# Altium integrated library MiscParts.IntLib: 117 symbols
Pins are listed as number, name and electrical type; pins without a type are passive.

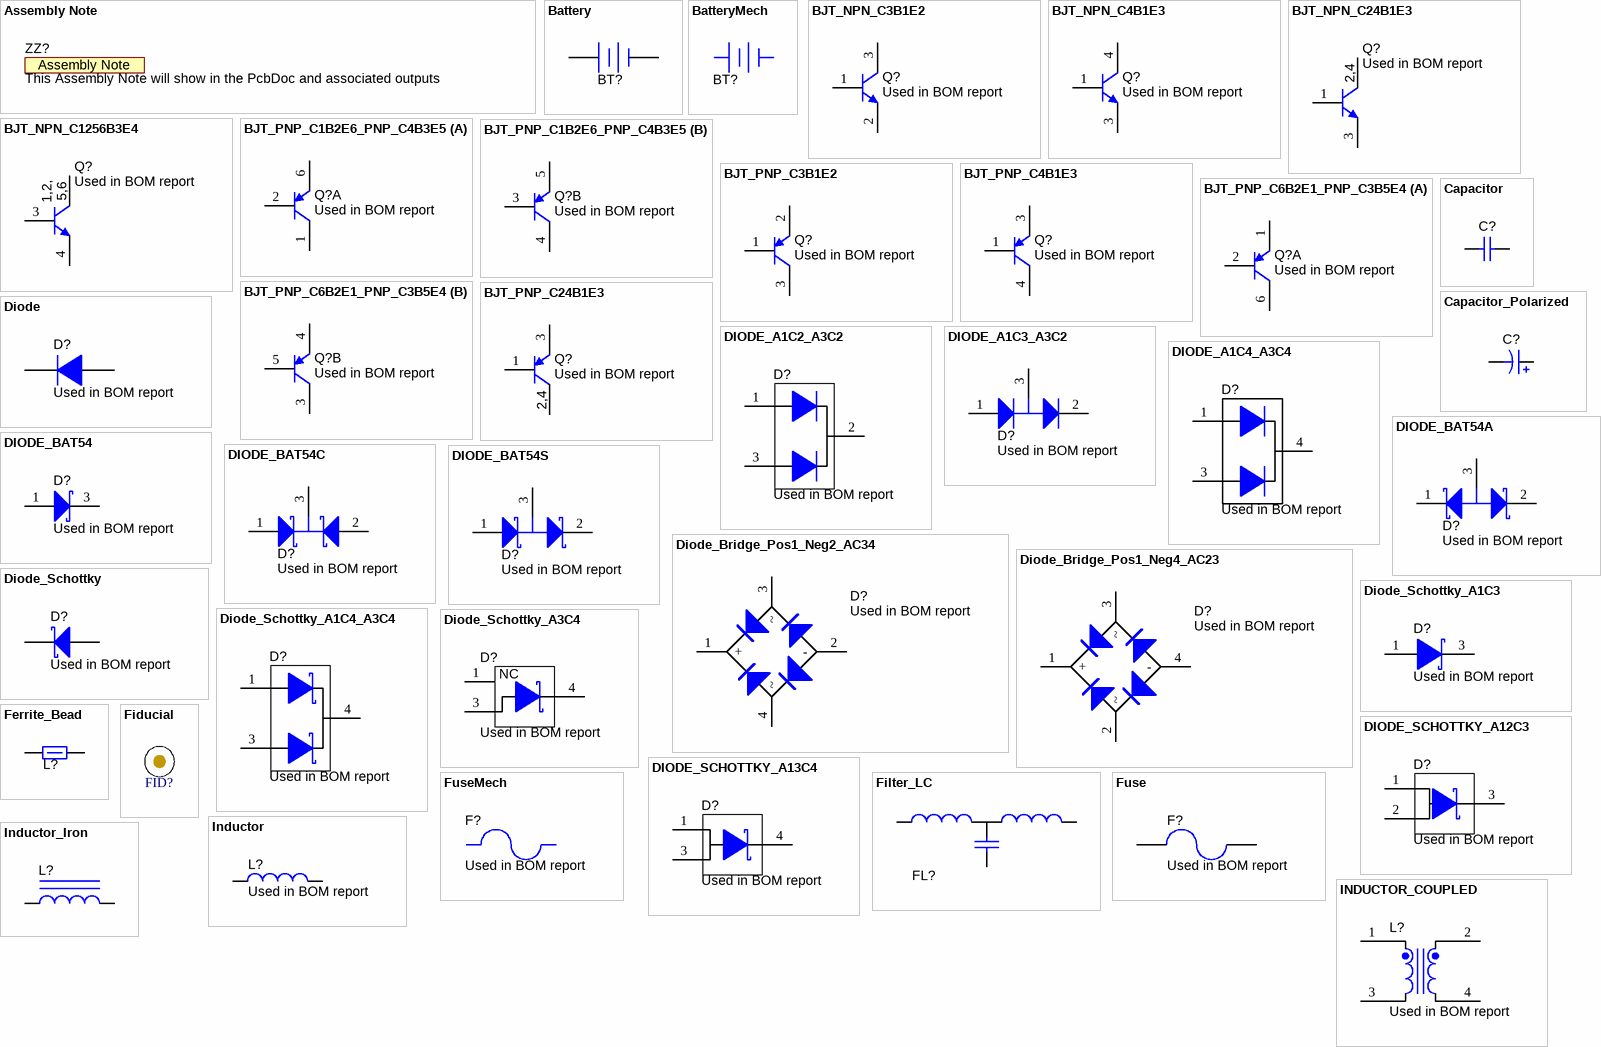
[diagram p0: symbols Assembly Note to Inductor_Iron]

## Assembly Note
designator ZZ?, comment This Assembly Note will show in the PcbDoc and associated outputs  (no BOM)
SymbolCreator: codlsc
footprint AssemblyNote

## Battery
designator BT?, comment Used in BOM report  (value not drawn)
Battery, [Technology], xV, xxmAh; U/M: EA
pins: 1 +, 2 -

## BatteryMech
designator BT?, comment Used in BOM report  (value not drawn)  (mechanical)
Battery, [Technology], xV, xxmAh; SymbolCreator: a0412235; U/M: EA

## BJT_NPN_C3B1E2
designator Q?, comment Used in BOM report
Transistor, NPN, xxV, xA, [PackageReference]; CompType: Bipolar Transistor; U/M: EA
simulation model NPN (Altium default NPN model)
pins: 1 B, 2 E, 3 C

## BJT_NPN_C4B1E3
designator Q?, comment Used in BOM report
Transistor, NPN, xxV, xA, [PackageReference]; CompType: Bipolar Transistor; U/M: EA
simulation model NPN (Altium default NPN model)
pins: 1 B, 3 E, 4 C

## BJT_NPN_C24B1E3
designator Q?, comment Used in BOM report
Transistor, NPN, xxV, xA, [PackageReference]; SymbolCreator: a0412235; CompType: Bipolar Transistor; U/M: EA
footprint SOT-89-3
simulation model NPN (Altium default NPN model)
pins: 1 B, 2 C, 3 E, 4 C

## BJT_NPN_C1256B3E4
designator Q?, comment Used in BOM report
Transistor, NPN, xxV, xA, [PackageReference]; CompType: Bipolar Transistor; U/M: EA
simulation model NPN (Altium default NPN model)
pins: 1 C, 2 C, 3 B, 4 E, 5 C, 6 C

## BJT_PNP_C1B2E6_PNP_C4B3E5
designator Q?, comment Used in BOM report
Transistor, NPN, xxV, xA, [PackageReference]; CompType: Bipolar Transistor; U/M: EA
part A pins: 1 C, 2 B, 6 E
part B pins: 3 B, 4 C, 5 E

## BJT_PNP_C3B1E2
designator Q?, comment Used in BOM report
Transistor, NPN, xxV, xA, [PackageReference]; CompType: Bipolar Transistor; U/M: EA
simulation model PNP (Altium default PNP model)
pins: 1 B, 2 E, 3 C

## BJT_PNP_C4B1E3
designator Q?, comment Used in BOM report
Transistor, NPN, xxV, xA, [PackageReference]; CompType: Bipolar Transistor; U/M: EA
simulation model PNP (Altium default PNP model)
pins: 1 B, 3 E, 4 C

## BJT_PNP_C6B2E1_PNP_C3B5E4
designator Q?, comment Used in BOM report
Transistor, NPN, xxV, xA, [PackageReference]; CompType: Bipolar Transistor; U/M: EA
part A pins: 1 E, 2 B, 6 C
part B pins: 3 C, 4 E, 5 B

## BJT_PNP_C24B1E3
designator Q?, comment Used in BOM report
Transistor, NPN, xxV, xA, [PackageReference]; CompType: Bipolar Transistor; U/M: EA
simulation model PNP (Altium default PNP model)
pins: 1 B, 2 C, 3 E, 4 C

## Capacitor
designator C?, comment Used in BOM report  (value not drawn)
CAP, CERM, xxxF, xxV, [TempCo], xx%, [PackageReference]; Polarized: N; CompType: Capacitor; U/M: EA
signal-integrity model Cap
simulation model Cap
footprint TBD
footprint 0201
footprint 0402
footprint 0603
footprint 0603_HV
footprint 0805
footprint 0805_HV
footprint 1206
footprint 1210
footprint 1808
footprint 1812
footprint 1825
footprint 2220
footprint 2225
footprint 0508
footprint 0612
pins: 1, 2

## Capacitor_Polarized
designator C?, comment Used in BOM report  (value not drawn)
CAP, [Technology], xxxF, xxV, +/-xx%, xxOhm ESR, [MountType]; Polarized: Y; CompType: Capacitor; U/M: EA
signal-integrity model Cap
simulation model Cap
footprint TBD
footprint 3216-18
footprint 3528-12
footprint 3528-21
footprint 6032-15
footprint 6032-28
footprint 7360-38
footprint 7343-20
footprint 7343-31
footprint 7343-43
footprint 7361-38
footprint CAPPR5-10x20
footprint CAPPR5-12.5x20
footprint CAPPR5-12.5x25
footprint CAPPR7.5-16x20
footprint CAPPR7.5-16x25
footprint CAPPR7.5-16x31.5
footprint CAPPR7.5-18x20
footprint CAPPR7.5-18x25
footprint CAPPR7.5-18x31.5
footprint CAPPR7.5-18x40
footprint CAPSMT_6_UD
footprint CAPSMT_6_UE
footprint CAPSMT_62_D55
footprint CAPSMT_62_D61
footprint CAPSMT_62_E55
footprint CAPSMT_62_E60
footprint CAPSMT_62_E61
footprint CAPSMT_62_F55
footprint CAPSMT_62_F60
footprint CAPSMT_62_F61
footprint CAPSMT_62_F80
footprint CAPSMT_62_H63
footprint CAPSMT_62_H70
footprint CAPSMT_62_H80
footprint CAPSMT_62_HA0
footprint CAPSMT_62_HC0
footprint CAPSMT_62_J80
footprint CAPSMT_62_JA0
footprint CAPSMT_62_JC0
footprint CAPSMT_62_KE0
footprint CAPSMT_62_KG5
footprint CAPSMT_62_LH0
footprint CAPSMT_62_LN0
footprint CAPSMT_62_MH0
footprint CAPSMT_62_MN0
footprint CC_CASEC
footprint CC_CASED
footprint CC_CASER
footprint SM_RADIAL_4MM
footprint SM_RADIAL_5MM
footprint SM_RADIAL_6.3AMM
footprint SM_RADIAL_6.3BMM
footprint SM_RADIAL_8MM
footprint SM_RADIAL_10AMM
footprint SM_RADIAL_10BMM
footprint SM_RADIAL_B
footprint SM_RADIAL_C
footprint SM_RADIAL_D
footprint SM_RADIAL_D8
footprint SM_RADIAL_E
footprint SM_RADIAL_F
footprint SM_RADIAL_G
footprint SM_RADIAL_H13
footprint SM_RADIAL_J16
footprint SM_RADIAL_K16
pins: 1 +, 2 -

## Diode
designator D?, comment Used in BOM report
Diode, [Type], xxxV, x.xxA, [PackageReference]; U/M: EA
signal-integrity model Diode
footprint TBD
footprint SMB
footprint SOD-123
simulation model DIODE (Altium default Diode model)
pins: 1 K, 2 A

## DIODE_A1C2_A3C2
designator D?, comment Used in BOM report
Diode, [Type], xxxV, x.xxA, [PackageReference]; U/M: EA
signal-integrity model Diode
footprint TBD-4
footprint TO-220AB
pins: 1 A, 2 K, 3 A

## DIODE_A1C3_A3C2
designator D?, comment Used in BOM report
Diode, [Type], xxxV, x.xxA, [PackageReference]; SymbolCreator: a0412235; U/M: EA
footprint TBD-4
footprint SOT-323
pins: 1 A, 2 K, 3 C
1 alternate drawing of the same symbol

## DIODE_A1C4_A3C4
designator D?, comment Used in BOM report
Diode, [Type], xxxV, x.xxA, [PackageReference]; U/M: EA
signal-integrity model Diode
footprint TBD-4
footprint DDPAK
footprint DPAK
pins: 1 A, 3 A, 4 K

## DIODE_BAT54
designator D?, comment Used in BOM report
Diode, Schottky, xxV, xxA, [PackageReference]; U/M: EA
signal-integrity model Model Name (Model Description)
footprint TBD-4
footprint SOT-23
footprint SOT-523
pins: 1 A, 3 K

## DIODE_BAT54A
designator D?, comment Used in BOM report
Diode, Schottky, xxV, xxA, [PackageReference]; U/M: EA
signal-integrity model Diode
footprint TBD-4
footprint SOT-23
footprint SOT-523
pins: 1 K1, 2 K2, 3 A
1 alternate drawing of the same symbol

## DIODE_BAT54C
designator D?, comment Used in BOM report
Diode, Schottky, xxV, xxA, [PackageReference]; U/M: EA
signal-integrity model Diode
footprint TBD-4
footprint SOT-23
footprint SOT-523
pins: 1 A1, 2 A2, 3 K
1 alternate drawing of the same symbol

## DIODE_BAT54S
designator D?, comment Used in BOM report
Diode, Schottky, xxV, xxA, [PackageReference]; U/M: EA
signal-integrity model Diode
footprint TBD-4
footprint SOT-23
footprint SOT-523
pins: 1 A, 2 K, 3 C
2 alternate drawings of the same symbol

## Diode_Bridge_Pos1_Neg2_AC34
designator D?, comment Used in BOM report
Diode, Switching-Bridge, xxxV, x.xA, [PackageReference]; CompType: Diode Bridge; U/M: EA
signal-integrity model Diode
footprint TBD-4
footprint DF-S
footprint GBU
footprint KBPM
footprint MINIDIP
pins: 1 +, 2 -, 3 ~, 4 ~

## Diode_Bridge_Pos1_Neg4_AC23
designator D?, comment Used in BOM report
Diode, Switching-Bridge, xxxV, x.xA, [PackageReference]; CompType: Diode Bridge; U/M: EA
footprint TBD-4
footprint DF-S
footprint GBU
footprint KBPM
footprint MINIDIP
pins: 1 +, 2 ~, 3 ~, 4 -

## Diode_Schottky
designator D?, comment Used in BOM report
Diode, Schottky, xxV, xxA, [PackageReference]; U/M: EA
signal-integrity model Diode
footprint TBD
footprint powerDI123
footprint POWERMITE
footprint SMA
footprint SMB
footprint SMC
footprint SOD-123
footprint SOD-123FL
footprint SOD-323
footprint SOD-523
simulation model SKYDIODE (Altium default Schottky Diode model)
pins: 1 K, 2 A

## Diode_Schottky_A1C3
designator D?, comment Used in BOM report
Diode, Schottky, xxV, xxA, [PackageReference]; U/M: EA
signal-integrity model Diode
footprint TBD-4
footprint SOT-23
footprint SOT-523
pins: 1 A, 3 K

## Diode_Schottky_A1C4_A3C4
designator D?, comment Used in BOM report
Diode, Schottky, xxV, xxA, [PackageReference]; U/M: EA
signal-integrity model Diode
footprint TBD-4
footprint DDPAK
footprint DPAK
pins: 1 A, 3 A, 4 K

## Diode_Schottky_A3C4
designator D?, comment Used in BOM report
Diode, Schottky, xxV, xxA, [PackageReference]; U/M: EA
signal-integrity model Diode
footprint TBD-4
footprint DDPAK
footprint DPAK
pins: 1 NC, 3 A, 4 K

## DIODE_SCHOTTKY_A12C3
designator D?, comment Used in BOM report
Diode, Schottky, xxV, xxA, [PackageReference]; U/M: EA
signal-integrity model Diode
footprint TBD-4
footprint PowerDI5
pins: 1 A, 2 A, 3 K

## DIODE_SCHOTTKY_A13C4
designator D?, comment Used in BOM report
Diode, Schottky, xxV, xxA, [PackageReference]; U/M: EA
signal-integrity model Diode
footprint TBD-4
footprint DDPAK
footprint DPAK
pins: 1 A, 3 A, 4 K

## Ferrite_Bead
designator L?, comment Used in BOM report  (value not drawn)
xA Ferrite Bead, xxx ohm @ 100MHz; U/M: EA
footprint TBD
footprint 0402
footprint 0603
footprint 0805
footprint 1206
footprint 1210
footprint 1812
footprint 2220
pins: 1, 2

## Fiducial
designator FID?  (value not drawn)
Fiducial mark.  There is nothing to buy or mount.; SymbolCreator: codlsc
footprint Fiducial10-30
footprint Fiducial10-20
footprint Fiducial15-30
footprint Fiducial20-40
footprint Fiducial6.4-20

## Filter_LC
designator FL?, comment Used in BOM report  (value not drawn)
CompType: LC Filter; U/M: EA
pins: 1, 2, 3

## Fuse
designator F?, comment Used in BOM report
Fuse, xxA, xxxV, [MountType]; U/M: EA
footprint TBD
footprint 6125FA
footprint PicoSMF459
footprint PicoSMF460
footprint SLOBLO452
simulation model Fuse (Altium default FUSE subcircuit)
pins: 1, 2

## FuseMech
designator F?, comment Used in BOM report  (mechanical)
Fuse, xxA, xxxV, [MountType]; SymbolCreator: a0412235; U/M: EA

## Inductor
designator L?, comment Used in BOM report
Inductor, [Technology], [Material], xxuH, xxA, x.xx ohm, [MountType]; U/M: EA
signal-integrity model Inductor
simulation model Inductor
pins: 1, 2

## INDUCTOR_COUPLED
designator L?, comment Used in BOM report
Coupled Inductor, xxuH, xxA, x.xx ohm, +/-xx%, [MountType]; U/M: EA
pins: 1, 2, 3, 4

## Inductor_Iron
designator L?, comment Used in BOM report  (value not drawn)
Inductor, [Technology], [Material], xxuH, xxA, x.xx ohm, [MountType]; U/M: EA
signal-integrity model Inductor
simulation model Inductor
pins: 1, 2

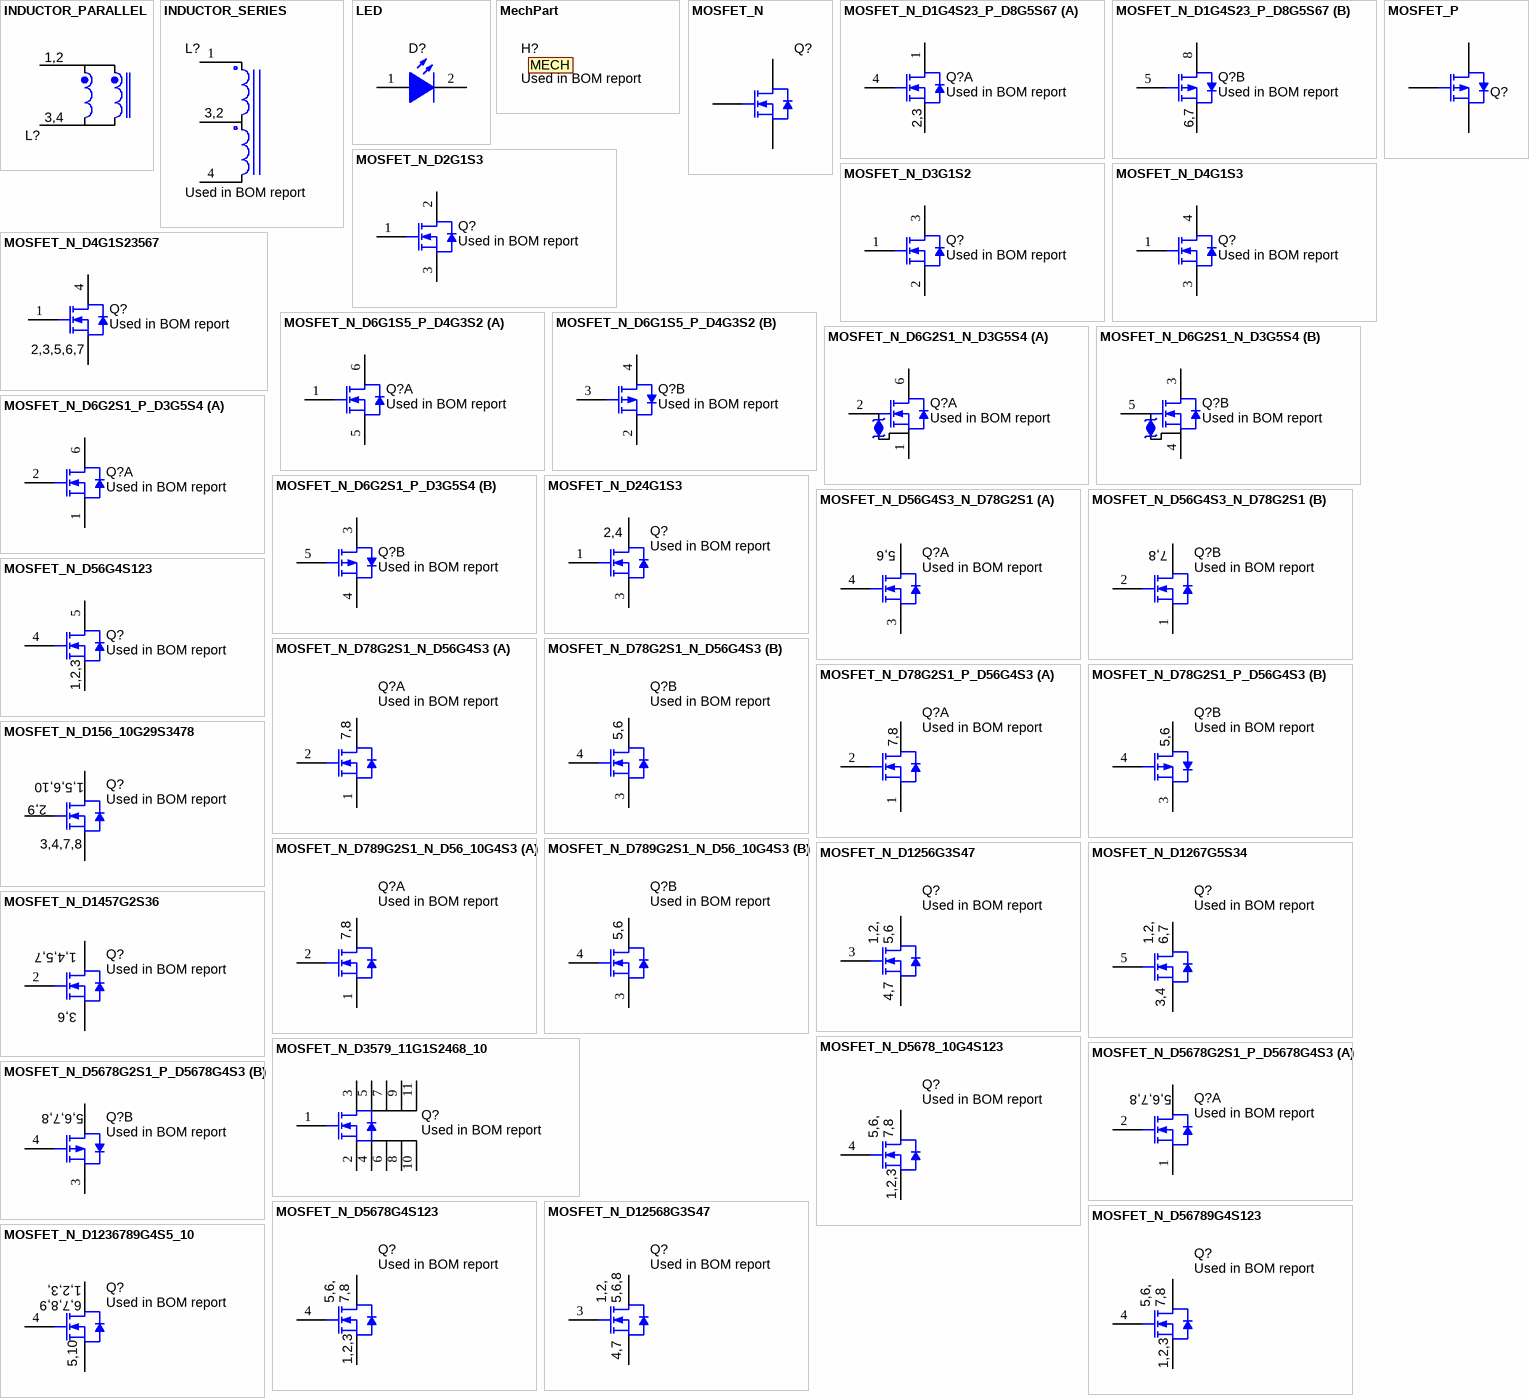
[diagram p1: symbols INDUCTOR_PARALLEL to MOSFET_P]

## INDUCTOR_PARALLEL
designator L?, comment Used in BOM report  (value not drawn)
Coupled Inductor, xxuH, xxA, x.xx ohm, +/-xx%, [MountType]; U/M: EA
pins: 1, 2, 3, 4

## INDUCTOR_SERIES
designator L?, comment Used in BOM report
Coupled Inductor, xxuH, xxA, x.xx ohm, +/-xx%, [MountType]; U/M: EA
pins: 1, 2, 3, 4

## LED
designator D?, comment Used in BOM report  (value not drawn)
LED, [Color], [MountType]; U/M: EA
signal-integrity model Diode
pins: 1 A, 2 K

## MechPart
designator H?, comment Used in BOM report  (mechanical)
Will add component to BOM.  Useful for cables, nuts, etc. not in libraries; SymbolCreator: codlsc; CompType: Mechanical; U/M: EA

## MOSFET_N
designator Q?, comment Used in BOM report  (value not drawn)
MOSFET, N-CH, xxV, xxxA, [PackageReferernce]; U/M: EA
simulation model NMOS (Altium default N-channel MOSFET)
pins: 1 D, 2 G, 3 S

## MOSFET_N_D1G4S23_P_D8G5S67
designator Q?, comment Used in BOM report
N- and P- Channel MOSFET; U/M: EA
footprint TSSOP-8
part A pins: 1 D, 2 S, 3 S, 4 G
part B pins: 5 G, 6 S, 7 S, 8 D

## MOSFET_N_D2G1S3
designator Q?, comment Used in BOM report
MOSFET, N-CH, xxV, xxxA, [PackageReference]; U/M: EA
footprint TO-220AB
pins: 1 G, 2 D, 3 S
1 alternate drawing of the same symbol

## MOSFET_N_D3G1S2
designator Q?, comment Used in BOM report
MOSFET, N-CH, xxV, xxxA, SOT-23; U/M: EA
footprint SOT-23
pins: 1 G, 2 S, 3 D

## MOSFET_N_D4G1S3
designator Q?, comment Used in BOM report
MOSFET, N-CH, xxV, xxxA, DPAK; U/M: EA
footprint DPAK
pins: 1 G, 3 S, 4 D

## MOSFET_N_D4G1S23567
designator Q?, comment Used in BOM report
MOSFET, N-CH, xxV, xxxA, [PackageReference]; SymbolCreator: a0412235; U/M: EA
footprint DDPAK-7
pins: 1 G, 2 S, 3 S, 4 D, 5 S, 6 S, 7 S

## MOSFET_N_D6G1S5_P_D4G3S2
designator Q?, comment Used in BOM report
Complementary N- and P- Channel MOSFET; U/M: EA
footprint TSOP-6
part A pins: 1 G, 5 S, 6 D
part B pins: 2 S, 3 G, 4 D

## MOSFET_N_D6G2S1_N_D3G5S4
designator Q?, comment Used in BOM report
Dual N-Channel MOSFET; U/M: EA
footprint SOT-563
part A pins: 1 S, 2 G, 6 D
part B pins: 3 D, 4 S, 5 G

## MOSFET_N_D6G2S1_P_D3G5S4
designator Q?, comment Used in BOM report
Complementary N- and P- Channel MOSFET; U/M: EA
footprint SOT-563
part A pins: 1 S, 2 G, 6 D
part B pins: 3 D, 4 S, 5 G

## MOSFET_N_D24G1S3
designator Q?, comment Used in BOM report
MOSFET, N-CH, xxV, xxxA, [PackageReference]; U/M: EA
footprint SOT-223
footprint SOT-223M
footprint SOT-223L
pins: 1 G, 2 D, 3 S, 4 D

## MOSFET_N_D56G4S3_N_D78G2S1
designator Q?, comment Used in BOM report
Dual N-Channel MOSFET; U/M: EA
footprint SOIC-8
part A pins: 3 S, 4 G, 5 D, 6 D
part B pins: 1 S, 2 G, 7 D, 8 D

## MOSFET_N_D56G4S123
designator Q?, comment Used in BOM report
MOSFET, N-CH, xxV, xxxA, LFPAK; U/M: EA
footprint LFPAK
footprint TRANS_DFN5
pins: 1 S, 2 S, 3 S, 4 G, 5 D, 6 D

## MOSFET_N_D78G2S1_N_D56G4S3
designator Q?, comment Used in BOM report
Dual N-Channel MOSFET; U/M: EA
footprint SOIC-8
footprint SOT1205
part A pins: 1 S, 2 G, 7 D, 8 D
part B pins: 3 S, 4 G, 5 D, 6 D

## MOSFET_N_D78G2S1_P_D56G4S3
designator Q?, comment Used in BOM report
N- and P- Channel MOSFET; SymbolCreator: a0412235; U/M: EA
footprint SOIC-8
part A pins: 1 S, 2 G, 7 D, 8 D
part B pins: 3 S, 4 G, 5 D, 6 D

## MOSFET_N_D156_10G29S3478
designator Q?, comment Used in BOM report
MOSFET, N-CH, xxV, xxxA, [PackageReference]; U/M: EA
footprint PolarPAK
pins: 1 D, 2 G, 3 S, 4 S, 5 D, 6 D, 7 S, 8 S, 9 G, 10 D

## MOSFET_N_D789G2S1_N_D56_10G4S3
designator Q?, comment Used in BOM report
Dual N-Channel MOSFET; U/M: EA
footprint PG-TDSON-8_Dual
footprint PowerPAK_1212-8_Dual
footprint PowerPAK_1212-8_Dual_NoVias
part A pins: 1 S, 2 G, 7 D, 8 D, 9 D
part B pins: 3 S, 4 G, 5 D, 6 D, 10 D

## MOSFET_N_D1256G3S47
designator Q?, comment Used in BOM report
MOSFET, N-CH, xxV, xxxA, [PackageReference]; SymbolCreator: a0799628; U/M: EA
footprint PowerPAK_SC-70
pins: 1 D, 2 D, 3 G, 4 S, 5 D, 6 D, 7 S

## MOSFET_N_D1267G5S34
designator Q?, comment Used in BOM report
MOSFET, N-CH, xxV, xxA, DirectFET MT; U/M: EA
footprint DirectFET MT
pins: 1 D, 2 D, 3 S, 4 S, 5 G, 6 D, 7 D

## MOSFET_N_D1457G2S36
designator Q?, comment Used in BOM report
MOSFET, N-CH, xxV, xxxA, [PackageReference]; U/M: EA
footprint DirectFET_MT
footprint DirectFET_MN
pins: 1 D, 2 G, 3 S, 4 D, 5 D, 6 S, 7 D

## MOSFET_N_D3579_11G1S2468_10
designator Q?, comment Used in BOM report
MOSFET, N-CH, xxV, xxxA, [PackageReference]; SymbolCreator: a0412235; U/M: EA
footprint TRANS_EPC2001
pins: 1 G, 2 S, 3 D, 4 S, 5 D, 6 S, 7 D, 8 S, 9 D, 10 S, 11 D

## MOSFET_N_D5678_10G4S123
designator Q?, comment Used in BOM report
MOSFET, N-CH, xxV, xxxA, [PackageReference]; U/M: EA
footprint TRANS_NexFET_Q5C
pins: 1 S, 2 S, 3 S, 4 G, 5 D, 6 D, 7 D, 8 D, 10 D

## MOSFET_N_D5678G2S1_P_D5678G4S3
designator Q?, comment Used in BOM report
N- and P- Channel MOSFET; U/M: EA
footprint SOIC-8
pins on every part: 5 D, 6 D, 7 D, 8 D
part A pins: 1 S, 2 G
part B pins: 3 S, 4 G

## MOSFET_N_D5678G4S123
designator Q?, comment Used in BOM report
MOSFET, N-CH, xxV, xxxA, SOIC-8; U/M: EA
footprint SOIC-8
pins: 1 S, 2 S, 3 S, 4 G, 5 D, 6 D, 7 D, 8 D
1 alternate drawing of the same symbol

## MOSFET_N_D12568G3S47
designator Q?, comment Used in BOM report
MOSFET, N-CH, xxV, xxxA, [PackageReference]; U/M: EA
footprint TRANS_NexFET_Q2
pins: 1 D, 2 D, 3 G, 4 S, 5 D, 6 D, 7 S, 8 D

## MOSFET_N_D56789G4S123
designator Q?, comment Used in BOM report
MOSFET, N-CH, xxV, xxxA, [PackageReference]; U/M: EA
footprint PowerPAK_SO-8
footprint PG-TDSON-8
pins: 1 S, 2 S, 3 S, 4 G, 5 D, 6 D, 7 D, 8 D, 9 D

## MOSFET_N_D1236789G4S5_10
designator Q?, comment Used in BOM report
MOSFET, N-CH, xxV, xxxA, [PackageReference]; U/M: EA
footprint PowerPAK_ChipFET
pins: 1 D, 2 D, 3 D, 4 G, 5 S, 6 D, 7 D, 8 D, 9 D, 10 S

## MOSFET_P
designator Q?, comment Used in BOM report  (value not drawn)
MOSFET, P-CH, xxV, xxxA, [PackageReference]; U/M: EA
simulation model PMOS (Altium default P-channel MOSFET)
pins: 1 D, 2 G, 3 S

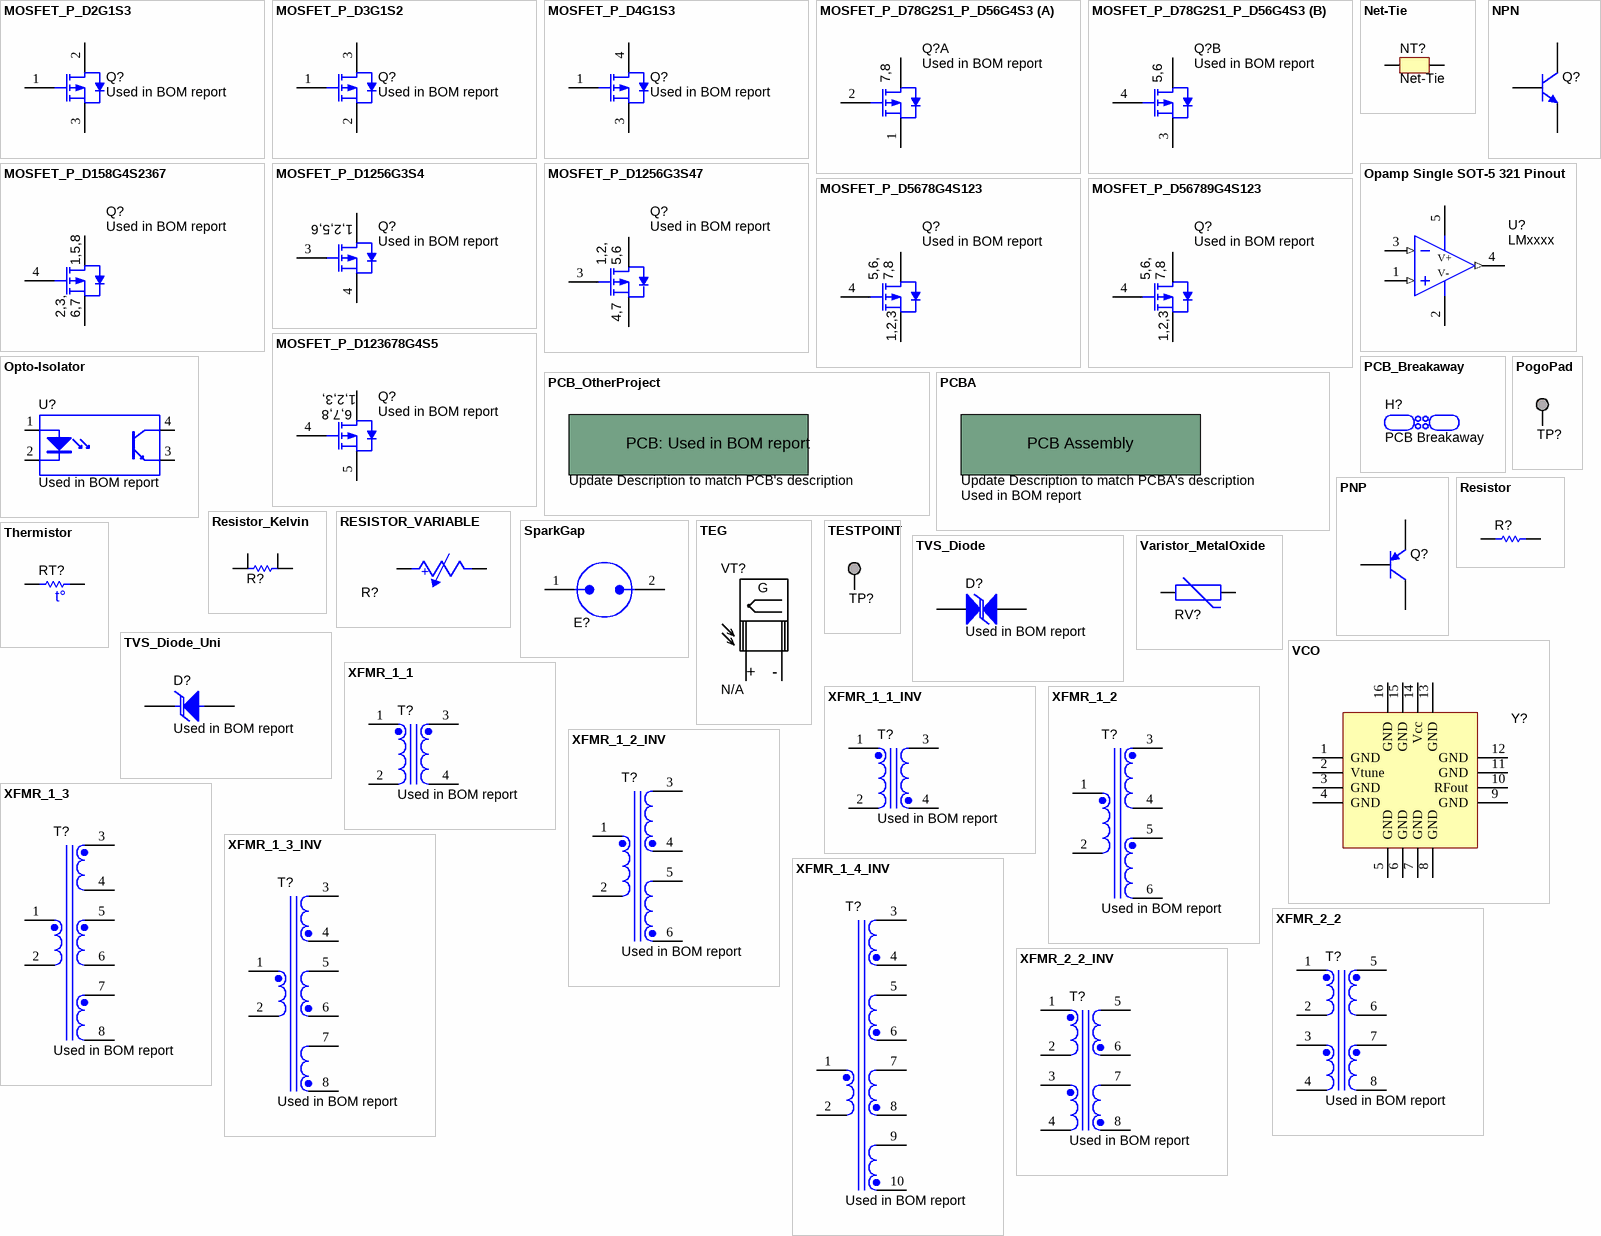
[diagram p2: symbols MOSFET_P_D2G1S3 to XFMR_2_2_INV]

## MOSFET_P_D2G1S3
designator Q?, comment Used in BOM report
MOSFET, P-CH, xxV, xxxA, [PackageReference]; U/M: EA
pins: 1 G, 2 D, 3 S

## MOSFET_P_D3G1S2
designator Q?, comment Used in BOM report
MOSFET, P-CH, xxV, xxxA, [PackageReference]; U/M: EA
footprint SOT-23
footprint SOT-323
footprint SSOT-3
pins: 1 G, 2 S, 3 D

## MOSFET_P_D4G1S3
designator Q?, comment Used in BOM report
MOSFET, P-CH, xxV, xxxA, [PackageReference]; U/M: EA
footprint DPAK
footprint DDPAK
footprint TO-252
footprint TO-268
pins: 1 G, 3 S, 4 D

## MOSFET_P_D78G2S1_P_D56G4S3
designator Q?, comment Used in BOM report
Dual P-Channel MOSFET; U/M: EA
part A pins: 1 S, 2 G, 7 D, 8 D, 9 DAP
part B pins: 3 S, 4 G, 5 D, 6 D, 10 DAP

## MOSFET_P_D158G4S2367
designator Q?, comment Used in BOM report
MOSFET, P-CH, xxV, xxxA, TSSOP-8; U/M: EA
footprint TSSOP-8
pins: 1 D, 2 S, 3 S, 4 G, 5 D, 6 S, 7 S, 8 D

## MOSFET_P_D1256G3S4
designator Q?, comment Used in BOM report
MOSFET, P-CH, xxV, xxxA, TSOP-6; U/M: EA
footprint TSOP-6
pins: 1 D, 2 D, 3 G, 4 S, 5 D, 6 D

## MOSFET_P_D1256G3S47
designator Q?, comment Used in BOM report
MOSFET, N-CH, xxV, xxxA, [PackageReference]; SymbolCreator: a0799628; U/M: EA
footprint PowerPAK_SC-70
pins: 1 D, 2 D, 3 G, 4 S, 5 D, 6 D, 7 S

## MOSFET_P_D5678G4S123
designator Q?, comment Used in BOM report
MOSFET, P-CH, xxV, xxxA, SOIC-8; U/M: EA
footprint SOIC-8
pins: 1 S, 2 S, 3 S, 4 G, 5 D, 6 D, 7 D, 8 D

## MOSFET_P_D56789G4S123
designator Q?, comment Used in BOM report
MOSFET, P-CH, xxV, xxxA, [PackageReference]; U/M: EA
footprint PowerPAK_SO-8
pins: 1 S, 2 S, 3 S, 4 G, 5 D, 6 D, 7 D, 8 D, 9 D

## MOSFET_P_D123678G4S5
designator Q?, comment Used in BOM report
MOSFET, P-CH, xxV, xxxA, 1206-8 SMD; U/M: EA
footprint 1206-8
pins: 1 D, 2 D, 3 D, 4 G, 5 S, 6 D, 7 D, 8 D

## Net-Tie
designator NT?  (net tie, no BOM)
Single point connection between nets.; SymbolCreator: codlsc
footprint Net-Tie_10mil (10mil net tie, no solder mask opening, no solder paste)
footprint NetTie_1206 (1206 pads tied by 10mil copper trace which can be cut.  Part can be placed on pads.)
footprint Net-Tie_0805_HV
footprint NetTie_1206_NoOverlay (1206 pads tied by 10mil copper trace which can be cut.  Part can be placed on pads.)
footprint Net-Tie_0805_HV_NoOverlay (0805_HV pads tied by 10mil copper trace which can be cut.  An 0805 part can be placed on pads.)
footprint Net-Tie_10milWide_30milLong
footprint Net-Tie_20milWide_60milLong
footprint NetTie_0603
footprint NetTie_0402
footprint Net-Tie_50milWide_30milLong
pins: 1, 2

## NPN
designator Q?, comment Used in BOM report  (value not drawn)
Transistor, NPN, xxV, xA, [PackageReference]; CompType: Bipolar Transistor; U/M: EA
signal-integrity model BJT
simulation model NPN (Altium default NPN model)
pins: 1 C, 2 B, 3 E

## Opamp Single SOT-5 321 Pinout
designator U?, comment LMxxxx
Generic Single Op Amp in SOT-5 w LMV321 pinout; Manufacturer: National Semiconductor; PartNumber: Used in BOM report; CompType: OpAmp IC; Sim Note: Shutdown not modeled; U/M: EA
footprint MF05A_N
footprint MF05A_L
footprint MF05A_M
simulation model LM324 (LM324 subcircuit)
pins: 1 IN+ (in), 2 V- (power), 3 IN- (in), 4 OUT (out), 5 V+ (power)
1 alternate drawing of the same symbol

## Opto-Isolator
designator U?, comment Used in BOM report
Optoisolator; U/M: EA
footprint TBD-4
footprint FOD121
footprint PS2501L
pins: 1 A, 2 K, 3 E, 4 C
1 alternate drawing of the same symbol

## PCB_Breakaway
designator H?, comment PCB Breakaway  (no BOM)
SymbolCreator: a0414679/a0412235
footprint PCB_Breakaway_160-580
footprint PCB_Breakaway_160-160
footprint TI_PCB_BREAKAWAY_93MIL
footprint TI_PCB_BREAKAWAY_300MIL
footprint TI_PCB_BREAKAWAY_1000MIL

## PCB_OtherProject
designator !PCB?, comment Update Description to match PCB's description  (mechanical)
Manufacturer: Any; PartNumber: Used in BOM report; SymbolCreator: a0412235; CompType: PCB; U/M: EA
1 alternate drawing of the same symbol

## PCBA
designator !PCBA?, comment Update Description to match PCBA's description  PartNumber: Used in BOM report  (mechanical)
SymbolCreator: a0412235; CompType: PCBA; U/M: EA
1 alternate drawing of the same symbol

## PNP
designator Q?, comment Used in BOM report  (value not drawn)
Transistor, NPN, xxV, xA, [PackageReference]; CompType: Bipolar Transistor; U/M: EA
signal-integrity model BJT
simulation model PNP (Altium default PNP model)
pins: 1 C, 2 B, 3 E

## PogoPad
designator TP?, comment Pogo Pad  (value not drawn)  (no BOM)
Pad for Pogo Pin Connector; SymbolCreator: codlsc
footprint PogoPad
pins: 1

## Resistor
designator R?, comment Used in BOM report  (value not drawn)
RES, xxx ohm, x%, xW, [PackageReference]; CompType: Resistor; U/M: EA
signal-integrity model Resistor
simulation model Resistor
footprint TBD
footprint 0201
footprint 0402
footprint 0603
footprint 0603_HV
footprint 0805
footprint 0805_HV
footprint 1206
footprint 1210
footprint 1812
footprint 2010
footprint 2512
footprint 0508
footprint 0612
pins: 1, 2

## Resistor_Kelvin
designator R?, comment Used in BOM report  (value not drawn)
RES, xxx ohm, x%, xW, [PackageReference]; CompType: Resistor; U/M: EA
signal-integrity model Resistor
simulation model Resistor
footprint TBD-4
footprint WSL3637_0.001
footprint WSL3637_0.002
pins: 1, 2, 3, 4

## RESISTOR_VARIABLE
designator R?, comment Used in BOM report  (value not drawn)
RES, ADJ, xxx ohm, xxW; CompType: Resistor; U/M: EA
pins: 1, 2

## SparkGap
designator E?, comment N/A  (value not drawn)  (no BOM)
Spark Gap; SymbolCreator: a0412235
footprint SPARK_GAP2
pins: 1, 2

## TEG
designator VT?, comment N/A
TEG; SymbolCreator: a0411947
pins: 1 +, 2 -

## TESTPOINT
designator TP?  (value not drawn)  (no BOM)
TEST POINT.  No entry in BOM.
footprint TESTPOINT
footprint TP_VIA_018RND008
footprint TP_VIA_060RND040
footprint TP_25MIL-SMT
footprint TP_50MIL-25MILHOLE
footprint TP_60MIL-SMT
footprint TP_VIA_024RND014
footprint TP_50MIL-SMT
footprint TP_60MIL-SMT-155
pins: 1

## Thermistor
designator RT?, comment Used in BOM report  (value not drawn)
Thermistor xTC, xxx ohm, x%, [PackageReference]; U/M: EA
pins: 1, 2

## TVS_Diode
designator D?, comment Used in BOM report
Diode, TVS, Bi, xxxW, xxV, xx%, [PackageReference]; U/M: EA
footprint TBD
footprint SMB
pins: 1, 2

## TVS_Diode_Uni
designator D?, comment Used in BOM report
Diode, TVS, Uni, xxxW, xxV, xx%, [PackageReference]; U/M: EA
footprint TBD
footprint SMB
pins: 1 K, 2 A

## Varistor_MetalOxide
designator RV?, comment Used in BOM report  (value not drawn)
Varistor, xxxVAC, xxVDC, xxJ, [Diameter], [Package]; SymbolCreator: a0412235; CompType: MOV; U/M: EA
pins: 1, 2

## VCO
designator Y?, comment Used in BOM report  (value not drawn)
VCO, SMD; SymbolCreator: a0412235; U/M: EA
footprint OSC_CVCO55BE-16
pins: 1 GND (power), 2 Vtune, 3 GND (power), 4 GND (power), 5 GND (power), 6 GND (power), 7 GND (power), 8 GND (power), 9 GND (power), 10 RFout, 11 GND (power), 12 GND (power), 13 GND (power), 14 Vcc (power), 15 GND (power), 16 GND (power)

## XFMR_1_1
designator T?, comment Used in BOM report
1 Input 1 Output XFMR; SymbolCreator: a0412235; CompType: Transformer; U/M: EA
pins: 1, 2, 3, 4

## XFMR_1_1_INV
designator T?, comment Used in BOM report
1 Input 1 Output XFMR; CompType: Transformer; U/M: EA
pins: 1, 2, 3, 4

## XFMR_1_2
designator T?, comment Used in BOM report
1 Input 2 Output XFMR; CompType: Transformer; U/M: EA
pins: 1, 2, 3, 4, 5, 6

## XFMR_1_2_INV
designator T?, comment Used in BOM report
1 Input 2 Output XFMR; SymbolCreator: a0412235; CompType: Transformer; U/M: EA
pins: 1, 2, 3, 4, 5, 6

## XFMR_1_3
designator T?, comment Used in BOM report
1 Input 3 Output XFMR; CompType: Transformer; U/M: EA
pins: 1, 2, 3, 4, 5, 6, 7, 8

## XFMR_1_3_INV
designator T?, comment Used in BOM report
1 Input 3 Output XFMR; CompType: Transformer; U/M: EA
pins: 1, 2, 3, 4, 5, 6, 7, 8

## XFMR_1_4_INV
designator T?, comment Used in BOM report
1 Input 4 Output XFMR; CompType: Transformer; U/M: EA
pins: 1, 2 4, 3, 4, 5, 6, 7, 8, 9, 10

## XFMR_2_2
designator T?, comment Used in BOM report
2 Input 2 Output XFMR; CompType: Transformer; U/M: EA
pins: 1, 2, 3, 4, 5, 6, 7, 8

## XFMR_2_2_INV
designator T?, comment Used in BOM report
2 Input 2 Output XFMR; CompType: Transformer; U/M: EA
pins: 1, 2, 3, 4, 5, 6, 7, 8

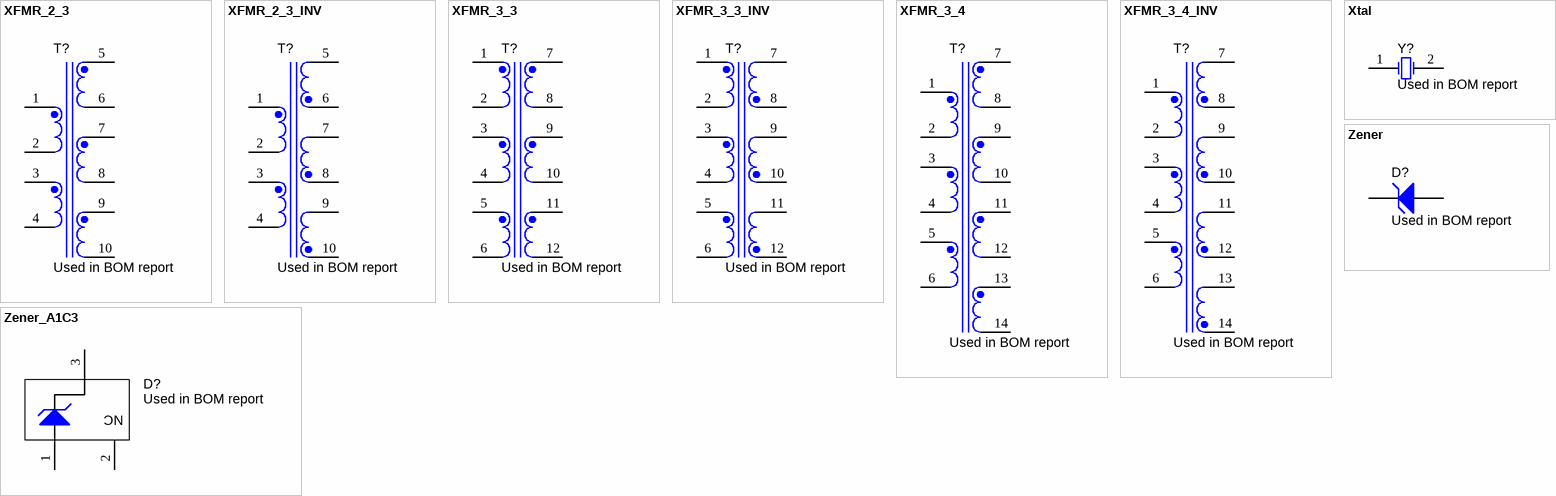
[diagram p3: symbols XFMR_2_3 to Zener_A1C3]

## XFMR_2_3
designator T?, comment Used in BOM report
2 Input 3 Output XFMR; CompType: Transformer; U/M: EA
pins: 1, 2, 3, 4, 5, 6, 7, 8, 9, 10

## XFMR_2_3_INV
designator T?, comment Used in BOM report
2 Input 3 Output XFMR; CompType: Transformer; U/M: EA
pins: 1, 2, 3, 4, 5, 6, 7, 8, 9, 10

## XFMR_3_3
designator T?, comment Used in BOM report
3 Input 3 Output XFMR; CompType: Transformer; U/M: EA
pins: 1, 2, 3, 4, 5, 6, 7, 8, 9, 10, 11, 12

## XFMR_3_3_INV
designator T?, comment Used in BOM report
3 Input 3 Output XFMR; CompType: Transformer; U/M: EA
pins: 1, 2, 3, 4, 5, 6, 7, 8, 9, 10, 11, 12

## XFMR_3_4
designator T?, comment Used in BOM report
3 Input 4 Output XFMR; CompType: Transformer; U/M: EA
pins: 1, 2, 3, 4, 5, 6, 7, 8, 9, 10, 11, 12, 13, 14

## XFMR_3_4_INV
designator T?, comment Used in BOM report
3 Input 4 Output XFMR; CompType: Transformer; U/M: EA
pins: 1, 2, 3, 4, 5, 6, 7, 8, 9, 10, 11, 12, 13, 14

## Xtal
designator Y?, comment Used in BOM report
Crystal, xxxMHz, xxpF, [MountType]; SymbolCreator: a0412235; U/M: EA
simulation model XTAL (Altium default crystal oscillator model)
pins: 1 OSC1, 2 OSC2

## Zener
designator D?, comment Used in BOM report
Diode, Zener, xxV, xxxmW, [PackageReference]; SymbolCreator: a0412235; U/M: EA
signal-integrity model Diode
footprint TBD
footprint powerDI123
footprint SMA
footprint SMB
footprint SOD-123
footprint SOD-323
simulation model Zener (Altium default Zener diode model)
pins: 1 K, 2 A

## Zener_A1C3
designator D?, comment Used in BOM report
Diode, Zener, xxV, xxxmW, [PackageReference]; U/M: EA
signal-integrity model Diode
footprint TBD-4
footprint SOT-23
pins: 1 A, 2 NC, 3 K
1 alternate drawing of the same symbol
